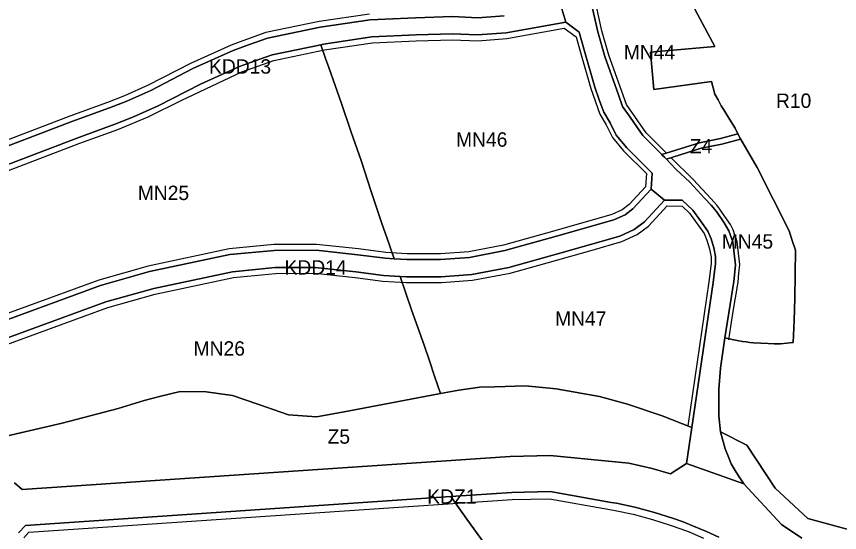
# Model space of a CAD drawing. Extents: x 7440055 to 7442242, y 5549003 to 5552256.
# Drawn here: x 7440932 to 7441503, y 5550092 to 5550451 of the extents above; entities that cross this region are included whole.
import ezdxf

# ---------------------------------------------------------------- set-up
doc = ezdxf.new("R2010")
doc.units = 0
for name, color, linetype in [('linie_rozgraniczajace', 7, 'Continuous'), ('linie_zabudowy_nieprzekraczalne', 7, 'Continuous'), ('oznaczenia_przeznaczen', 7, 'Continuous')]:
    doc.layers.add(name, color=color, linetype=linetype)

msp = doc.modelspace()

# ---------------------------------------------------------------- linework, layer by layer
at = {"layer": 'linie_rozgraniczajace'}
for points in [[(7441394.29, 5550472.38), (7441416.82, 5550430.21), (7441372.22, 5550426.18), (7441374.57, 5550400.14), (7441414.56, 5550405.9), (7441416.91, 5550396.96), (7441419.05, 5550392.95), (7441421.2, 5550388.93), (7441422.99, 5550386.03), (7441426.95, 5550379.71), (7441430.91, 5550373.39), (7441432.82, 5550369.44), (7441420.76, 5550366.05), (7441406.26, 5550363.26), (7441380.07, 5550354.95), (7441366.77, 5550368.28), (7441362.62, 5550374.26), (7441357.93, 5550381), (7441352.71, 5550388.52), (7441349.82, 5550396.59), (7441340.36, 5550423.2), (7441335.5, 5550440.32), (7441329.53, 5550467.05)], [(7441471.86, 5550239.66), (7441472.49, 5550255.04), (7441472.67, 5550271.74), (7441472.85, 5550288.43), (7441470.63, 5550295.2), (7441468.4, 5550301.97), (7441457.34, 5550323.93), (7441446.27, 5550345.89), (7441440.49, 5550355.87), (7441434.7, 5550365.84), (7441432.82, 5550369.44), (7441430.91, 5550373.39), (7441426.95, 5550379.71), (7441422.99, 5550386.03), (7441421.2, 5550388.93), (7441419.05, 5550392.95), (7441416.91, 5550396.96), (7441414.56, 5550405.9), (7441374.57, 5550400.14), (7441372.22, 5550426.18), (7441416.82, 5550430.21), (7441394.29, 5550472.38)], [(7441329.53, 5550467.05), (7441335.5, 5550440.32), (7441340.36, 5550423.2), (7441349.82, 5550396.59), (7441352.71, 5550388.52), (7441357.93, 5550381), (7441362.62, 5550374.26), (7441366.77, 5550368.28), (7441380.07, 5550354.95), (7441380.12, 5550354.9), (7441381.82, 5550353.2), (7441383.2, 5550351.74), (7441385.92, 5550348.88), (7441390.02, 5550344.57), (7441399.56, 5550335.73), (7441409.71, 5550324.78), (7441414.32, 5550319.83), (7441418.07, 5550315.46), (7441423.41, 5550307.56), (7441426.64, 5550301.88), (7441429.23, 5550294.21), (7441430.23, 5550286.15), (7441431.22, 5550278.1), (7441430.06, 5550266.64), (7441426.44, 5550245.04), (7441423.8, 5550227.45), (7441420.65, 5550206.43), (7441419.62, 5550191.63), (7441419.49, 5550178.36), (7441419.64, 5550173.38), (7441420.78, 5550162.2), (7441423.93, 5550150.36), (7441426.07, 5550145.2), (7441428.2, 5550140.03), (7441431.64, 5550134.2), (7441434.29, 5550130.17), (7441436.93, 5550126.14), (7441397.19, 5550140.1), (7441400.86, 5550165.23), (7441415.59, 5550266.1), (7441417.32, 5550279.15), (7441417.29, 5550284.03), (7441416.06, 5550290.07), (7441414.19, 5550296.41), (7441412.06, 5550301.63), (7441406.77, 5550308.95), (7441401.49, 5550316.27), (7441394.17, 5550323.21), (7441381.94, 5550323.31), (7441372.6, 5550330.82), (7441373.38, 5550342.16), (7441355.68, 5550359.58), (7441348.24, 5550368.4), (7441344.03, 5550377.05)], [(7441309.89, 5550458.66), (7441313.22, 5550447.05), (7441271.92, 5550439.75), (7441252.09, 5550438.15), (7441234.56, 5550438.88), (7441209.27, 5550438.15), (7441178.55, 5550436.76), (7441144.9, 5550431.76), (7441143.14, 5550431.39), (7441109.37, 5550424.34), (7441096.97, 5550419.9), (7441086.77, 5550416.26), (7441059.58, 5550403.94), (7441030.19, 5550388.78), (7441012.97, 5550381.17), (7441000.7, 5550376.26), (7440974.34, 5550366.74), (7440870.42, 5550326.97)], [(7441344.03, 5550377.05), (7441339.64, 5550384.36), (7441336.58, 5550393.16), (7441333.52, 5550401.96), (7441326.29, 5550426.81), (7441322.58, 5550440.13), (7441313.22, 5550447.05), (7441309.89, 5550458.66)], [(7441270.6, 5550451.55), (7441252.14, 5550450.16), (7441234.63, 5550450.88), (7441208.82, 5550450.14), (7441177.39, 5550448.72), (7441142.79, 5550443.57), (7441106.11, 5550435.91), (7441092.93, 5550431.19), (7441082.28, 5550427.39), (7441054.35, 5550414.75), (7441025.01, 5550399.61), (7441008.32, 5550392.23), (7440996.43, 5550387.48), (7440970.15, 5550377.98), (7440866.42, 5550338.29)], [(7440866.42, 5550338.29), (7440970.15, 5550377.98), (7440996.43, 5550387.48), (7441008.32, 5550392.23), (7441025.01, 5550399.61), (7441054.35, 5550414.75), (7441082.28, 5550427.39), (7441092.93, 5550431.19), (7441106.11, 5550435.91), (7441142.79, 5550443.57), (7441177.39, 5550448.72), (7441208.82, 5550450.14), (7441234.63, 5550450.88), (7441252.14, 5550450.16), (7441270.6, 5550451.55)], [(7440870.42, 5550326.97), (7440974.34, 5550366.74), (7441000.7, 5550376.26), (7441012.97, 5550381.17), (7441030.19, 5550388.78), (7441059.58, 5550403.94), (7441086.77, 5550416.26), (7441096.97, 5550419.9), (7441109.37, 5550424.34), (7441143.14, 5550431.39), (7441146.48, 5550421.88), (7441148.72, 5550415.5), (7441153.13, 5550402.95), (7441157.53, 5550390.39), (7441164.33, 5550370.6), (7441171.13, 5550350.82), (7441178.21, 5550329.29), (7441185.29, 5550307.76), (7441190.56, 5550292.69), (7441194.14, 5550282.48), (7441187.86, 5550282.85), (7441168.84, 5550285.38), (7441139.84, 5550288.57), (7441110.77, 5550288.39), (7441079.99, 5550285.41), (7441024.25, 5550273.57), (7440990.2, 5550263.91), (7440905.47, 5550232.9)], [(7440905.47, 5550232.9), (7440990.2, 5550263.91), (7441024.25, 5550273.57), (7441079.99, 5550285.41), (7441110.77, 5550288.39), (7441139.84, 5550288.57), (7441168.84, 5550285.38), (7441187.86, 5550282.85), (7441194.14, 5550282.48), (7441202.98, 5550281.95), (7441226.36, 5550281.92), (7441246.5, 5550283.44), (7441271.01, 5550288.17), (7441306.75, 5550298.2), (7441346.7, 5550309.5), (7441354.56, 5550313.2), (7441359.92, 5550317.23), (7441372.6, 5550330.82), (7441381.94, 5550323.31), (7441367.95, 5550308.26), (7441360.78, 5550302.87), (7441350.92, 5550298.22), (7441310, 5550286.65), (7441273.77, 5550276.49), (7441248.09, 5550271.53), (7441226.8, 5550269.92), (7441202.61, 5550269.95), (7441198.33, 5550270.21), (7441186.71, 5550270.9), (7441167.4, 5550273.47), (7441139.22, 5550276.56), (7441111.38, 5550276.4), (7441081.82, 5550273.53), (7441027.14, 5550261.92), (7440993.91, 5550252.48), (7440909.66, 5550221.66)], [(7440909.66, 5550221.66), (7440993.91, 5550252.48), (7441027.14, 5550261.92), (7441081.82, 5550273.53), (7441111.38, 5550276.4), (7441139.22, 5550276.56), (7441167.4, 5550273.47), (7441186.71, 5550270.9), (7441198.33, 5550270.21), (7441206.14, 5550247.01), (7441214.93, 5550222.37), (7441218.56, 5550211.6), (7441222.2, 5550200.84), (7441226.25, 5550188.81), (7441210.46, 5550185.83), (7441159.26, 5550176.17), (7441140.08, 5550172.54), (7441120.61, 5550174.08), (7441099.35, 5550181.47), (7441081.82, 5550187.56), (7441063.42, 5550190.07), (7441045.43, 5550190.32), (7441031.05, 5550186.72), (7441020.37, 5550184.05), (7441002.5, 5550178.35), (7440963.57, 5550168.27), (7440924.49, 5550159.2)], [(7441559.01, 5550080.87), (7441481.52, 5550102.04), (7441458.62, 5550122.98), (7441439.11, 5550152.95), (7441420.78, 5550162.2), (7441419.64, 5550173.38), (7441419.49, 5550178.36), (7441419.62, 5550191.63), (7441420.65, 5550206.43), (7441423.8, 5550227.45), (7441428.93, 5550226.36), (7441433.58, 5550225.37), (7441436.09, 5550225.06), (7441438.59, 5550224.74), (7441441.1, 5550224.43), (7441443.61, 5550224.11), (7441448.75, 5550223.85), (7441453.9, 5550223.59), (7441458.14, 5550223.5), (7441462.39, 5550223.41), (7441466.81, 5550223.85), (7441471.23, 5550224.29), (7441471.86, 5550239.66)], [(7440924.49, 5550159.2), (7440963.57, 5550168.27), (7441002.5, 5550178.35), (7441020.37, 5550184.05), (7441031.05, 5550186.72), (7441045.43, 5550190.32), (7441063.42, 5550190.07), (7441081.82, 5550187.56), (7441099.35, 5550181.47), (7441120.61, 5550174.08), (7441140.08, 5550172.54), (7441159.26, 5550176.17), (7441210.46, 5550185.83), (7441226.25, 5550188.81), (7441238.99, 5550191.21), (7441253.65, 5550193.2), (7441263.99, 5550193.51), (7441285.35, 5550194.16), (7441306.62, 5550192.02), (7441336.66, 5550186.83), (7441356.08, 5550181.45), (7441380.19, 5550173.26), (7441400.86, 5550165.23), (7441397.19, 5550140.1), (7441386.07, 5550133.08), (7441373.38, 5550136.75), (7441357.19, 5550140.36), (7441302.35, 5550145.65), (7441274.78, 5550145.06), (7440935.61, 5550122.08), (7440930.37, 5550126.73)], [(7441477.25, 5550088.28), (7441463.14, 5550097.77), (7441436.93, 5550126.14), (7441434.29, 5550130.17), (7441431.64, 5550134.2), (7441428.2, 5550140.03), (7441426.07, 5550145.2), (7441423.93, 5550150.36), (7441420.78, 5550162.2), (7441439.11, 5550152.95), (7441458.62, 5550122.98), (7441481.52, 5550102.04), (7441559.01, 5550080.87)], [(7440930.37, 5550126.73), (7440935.61, 5550122.08), (7441274.78, 5550145.06), (7441302.35, 5550145.65), (7441357.19, 5550140.36), (7441373.38, 5550136.75), (7441386.07, 5550133.08), (7441397.19, 5550140.1), (7441436.93, 5550126.14), (7441463.14, 5550097.77), (7441477.25, 5550088.28)], [(7441419.58, 5550088.95), (7441411.06, 5550092.87), (7441400.89, 5550097.18), (7441394.87, 5550099.53), (7441387.49, 5550102.15), (7441374.97, 5550106.13), (7441361.25, 5550109.8), (7441348.57, 5550112.52), (7441344.83, 5550113.15), (7441302.43, 5550120.64), (7441275.89, 5550120.08), (7441233.41, 5550117.2), (7440937.99, 5550097.18), (7440933.14, 5550091.88)], [(7440933.14, 5550091.88), (7440937.99, 5550097.18), (7441233.41, 5550117.2), (7441244.66, 5550101.57), (7441257.4, 5550083.89)], [(7441257.4, 5550083.89), (7441244.66, 5550101.57), (7441233.41, 5550117.2), (7441275.89, 5550120.08), (7441302.43, 5550120.64), (7441344.83, 5550113.15), (7441348.57, 5550112.52), (7441361.25, 5550109.8), (7441374.97, 5550106.13), (7441387.49, 5550102.15), (7441394.87, 5550099.53), (7441400.89, 5550097.18), (7441411.06, 5550092.87), (7441419.58, 5550088.95)]]:
    msp.add_lwpolyline(points, dxfattribs=at)
for points in [[(7441143.14, 5550431.39), (7441144.9, 5550431.76), (7441178.55, 5550436.76), (7441209.27, 5550438.15), (7441234.56, 5550438.88), (7441252.09, 5550438.15), (7441271.92, 5550439.75), (7441313.22, 5550447.05), (7441322.58, 5550440.13), (7441326.29, 5550426.81), (7441333.52, 5550401.96), (7441336.58, 5550393.16), (7441339.64, 5550384.36), (7441344.03, 5550377.05), (7441348.24, 5550368.4), (7441355.68, 5550359.58), (7441373.38, 5550342.16), (7441372.6, 5550330.82), (7441359.92, 5550317.23), (7441354.56, 5550313.2), (7441346.7, 5550309.5), (7441306.75, 5550298.2), (7441271.01, 5550288.17), (7441246.5, 5550283.44), (7441226.36, 5550281.92), (7441202.98, 5550281.95), (7441194.14, 5550282.48), (7441190.56, 5550292.69), (7441185.29, 5550307.76), (7441178.21, 5550329.29), (7441171.13, 5550350.82), (7441164.33, 5550370.6), (7441157.53, 5550390.39), (7441153.13, 5550402.95), (7441148.72, 5550415.5), (7441146.48, 5550421.88)], [(7441380.07, 5550354.95), (7441406.26, 5550363.26), (7441420.76, 5550366.05), (7441432.82, 5550369.44), (7441434.7, 5550365.84), (7441434.56, 5550365.77), (7441421.68, 5550362.16), (7441407.25, 5550359.37), (7441383.2, 5550351.74), (7441381.82, 5550353.2), (7441380.12, 5550354.9)], [(7441383.2, 5550351.74), (7441407.25, 5550359.37), (7441421.68, 5550362.16), (7441434.56, 5550365.77), (7441434.7, 5550365.84), (7441440.49, 5550355.87), (7441446.27, 5550345.89), (7441457.34, 5550323.93), (7441468.4, 5550301.97), (7441470.63, 5550295.2), (7441472.85, 5550288.43), (7441472.67, 5550271.74), (7441472.49, 5550255.04), (7441471.86, 5550239.66), (7441471.23, 5550224.29), (7441466.81, 5550223.85), (7441462.39, 5550223.41), (7441458.14, 5550223.5), (7441453.9, 5550223.59), (7441448.75, 5550223.85), (7441443.61, 5550224.11), (7441441.1, 5550224.43), (7441438.59, 5550224.74), (7441436.09, 5550225.06), (7441433.58, 5550225.37), (7441428.93, 5550226.36), (7441423.8, 5550227.45), (7441426.44, 5550245.04), (7441430.06, 5550266.64), (7441431.22, 5550278.1), (7441430.23, 5550286.15), (7441429.23, 5550294.21), (7441426.64, 5550301.88), (7441423.41, 5550307.56), (7441418.07, 5550315.46), (7441414.32, 5550319.83), (7441409.71, 5550324.78), (7441399.56, 5550335.73), (7441390.02, 5550344.57), (7441385.92, 5550348.88)], [(7441198.33, 5550270.21), (7441202.61, 5550269.95), (7441226.8, 5550269.92), (7441248.09, 5550271.53), (7441273.77, 5550276.49), (7441310, 5550286.65), (7441350.92, 5550298.22), (7441360.78, 5550302.87), (7441367.95, 5550308.26), (7441381.94, 5550323.31), (7441394.17, 5550323.21), (7441401.49, 5550316.27), (7441406.77, 5550308.95), (7441412.06, 5550301.63), (7441414.19, 5550296.41), (7441416.06, 5550290.07), (7441417.29, 5550284.03), (7441417.32, 5550279.15), (7441415.59, 5550266.1), (7441400.86, 5550165.23), (7441380.19, 5550173.26), (7441356.08, 5550181.45), (7441336.66, 5550186.83), (7441306.62, 5550192.02), (7441285.35, 5550194.16), (7441263.99, 5550193.51), (7441253.65, 5550193.2), (7441238.99, 5550191.21), (7441226.25, 5550188.81), (7441222.2, 5550200.84), (7441218.56, 5550211.6), (7441214.93, 5550222.37), (7441206.14, 5550247.01)]]:
    msp.add_lwpolyline(points, close=True, dxfattribs=at)
at = {"layer": 'linie_zabudowy_nieprzekraczalne'}
for points in [[(7441383.29, 5550355.97), (7441369.09, 5550370.21), (7441355.41, 5550389.9), (7441343.22, 5550424.11), (7441338.41, 5550441.05), (7441332.45, 5550467.75)], [(7441177.01, 5550452.71), (7441142.08, 5550447.51), (7441105.02, 5550439.77), (7441091.58, 5550434.96), (7441080.78, 5550431.1), (7441052.61, 5550418.35), (7441023.29, 5550403.22), (7441006.76, 5550395.92), (7440995.01, 5550391.22), (7440968.76, 5550381.73), (7440866.57, 5550342.63)], [(7440873.33, 5550323.8), (7440975.73, 5550362.99), (7441002.15, 5550372.53), (7441023.23, 5550381.33), (7441046.62, 5550392.76), (7441088.31, 5550412.56), (7441110.46, 5550420.48), (7441145.6, 5550427.82), (7441178.94, 5550432.78), (7441209.41, 5550434.16), (7441234.53, 5550434.87), (7441252.17, 5550434.15), (7441272.43, 5550435.78), (7441312.23, 5550442.81), (7441320.4, 5550436.76), (7441323.41, 5550425.99), (7441330.67, 5550401.04), (7441336.91, 5550383.08), (7441341.39, 5550375.62), (7441345.7, 5550366.75), (7441353.48, 5550357.54), (7441369.35, 5550341.92)], [(7441401.61, 5550337.92), (7441386.44, 5550352.77)], [(7441369.35, 5550341.92), (7441368.71, 5550332.51), (7441357.23, 5550320.22), (7441352.48, 5550316.65), (7441345.29, 5550313.26), (7441305.66, 5550302.05), (7441270.08, 5550292.07), (7441245.97, 5550287.41), (7441226.21, 5550285.92), (7441203.1, 5550285.95), (7441188.24, 5550286.83), (7441169.33, 5550289.35), (7441140.05, 5550292.57), (7441110.56, 5550292.39), (7441079.38, 5550289.37), (7441023.28, 5550277.45), (7440988.97, 5550267.71), (7440905.6, 5550237.21)], [(7441408, 5550331.04), (7441401.81, 5550337.71)], [(7441414.26, 5550324.29), (7441408, 5550331.04)], [(7441418.32, 5550319.78), (7441414.26, 5550324.29)], [(7440912.75, 5550218.53), (7440995.14, 5550248.68), (7441028.1, 5550258.03), (7441082.43, 5550269.57), (7441111.59, 5550272.4), (7441139.01, 5550272.56), (7441166.92, 5550269.5), (7441186.33, 5550266.91), (7441202.49, 5550265.95), (7441226.95, 5550265.92), (7441248.62, 5550267.55), (7441274.69, 5550272.59), (7441292.97, 5550277.72), (7441331.55, 5550288.59), (7441352.33, 5550294.47), (7441362.86, 5550299.43), (7441370.64, 5550305.28), (7441383.67, 5550319.3), (7441394.03, 5550319.21), (7441399.22, 5550314.29), (7441409.42, 5550300.16), (7441411.36, 5550295.42), (7441413.15, 5550289.35), (7441414.29, 5550283.72), (7441414.32, 5550279.34), (7441412.62, 5550266.52), (7441397.99, 5550166.34)], [(7441422.25, 5550314.35), (7441420.35, 5550317.12), (7441418.32, 5550319.78)], [(7441427.6, 5550306.26), (7441422.25, 5550314.35)], [(7441422.25, 5550314.35), (7441422.25, 5550314.35)], [(7441429.58, 5550302.57), (7441428.69, 5550304.45), (7441427.6, 5550306.26)], [(7441427.6, 5550306.26), (7441427.6, 5550306.26)], [(7441430.78, 5550299.01), (7441429.58, 5550302.57)], [(7441432.25, 5550294.27), (7441431.69, 5550296.67), (7441430.78, 5550299.01)], [(7441426.55, 5550226.26), (7441427.93, 5550235.42), (7441429.3, 5550244.58), (7441431.12, 5550255.42), (7441432.94, 5550266.26), (7441433.56, 5550272.42), (7441434.18, 5550278.58), (7441432.25, 5550294.27)], [(7440936.85, 5550088.53), (7440940.33, 5550092.33), (7441276.11, 5550115.08), (7441302.04, 5550115.63), (7441343.97, 5550108.23), (7441347.63, 5550107.61), (7441360.08, 5550104.94), (7441373.56, 5550101.33), (7441385.9, 5550097.41), (7441393.13, 5550094.85), (7441399, 5550092.55), (7441409.04, 5550088.3)]]:
    msp.add_lwpolyline(points, dxfattribs=at)
msp.add_arc((7441399.5, 5550335.71), 3.05, 40.8765, 46.3291, dxfattribs=at)

# ---------------------------------------------------------------- texts
at = {"layer": 'oznaczenia_przeznaczen'}
for s, p in [('MN44', (7441353.6, 5550421.18)), ('KDD13', (7441065.51, 5550411.26)), ('R10', (7441459.3, 5550387.43)), ('MN46', (7441237.07, 5550360.47)), ('Z4', (7441399.41, 5550355.86)), ('MN25', (7441016.01, 5550323.36)), ('MN45', (7441421.65, 5550289.58)), ('KDD14', (7441117.96, 5550271.56)), ('MN47', (7441305.84, 5550235.94)), ('MN26', (7441054.78, 5550215.17)), ('Z5', (7441147.84, 5550153.95)), ('KDZ1', (7441217.07, 5550112.2))]:
    msp.add_text(s, height=10, dxfattribs=at).set_placement(p)

doc.saveas('drawing.dxf')
